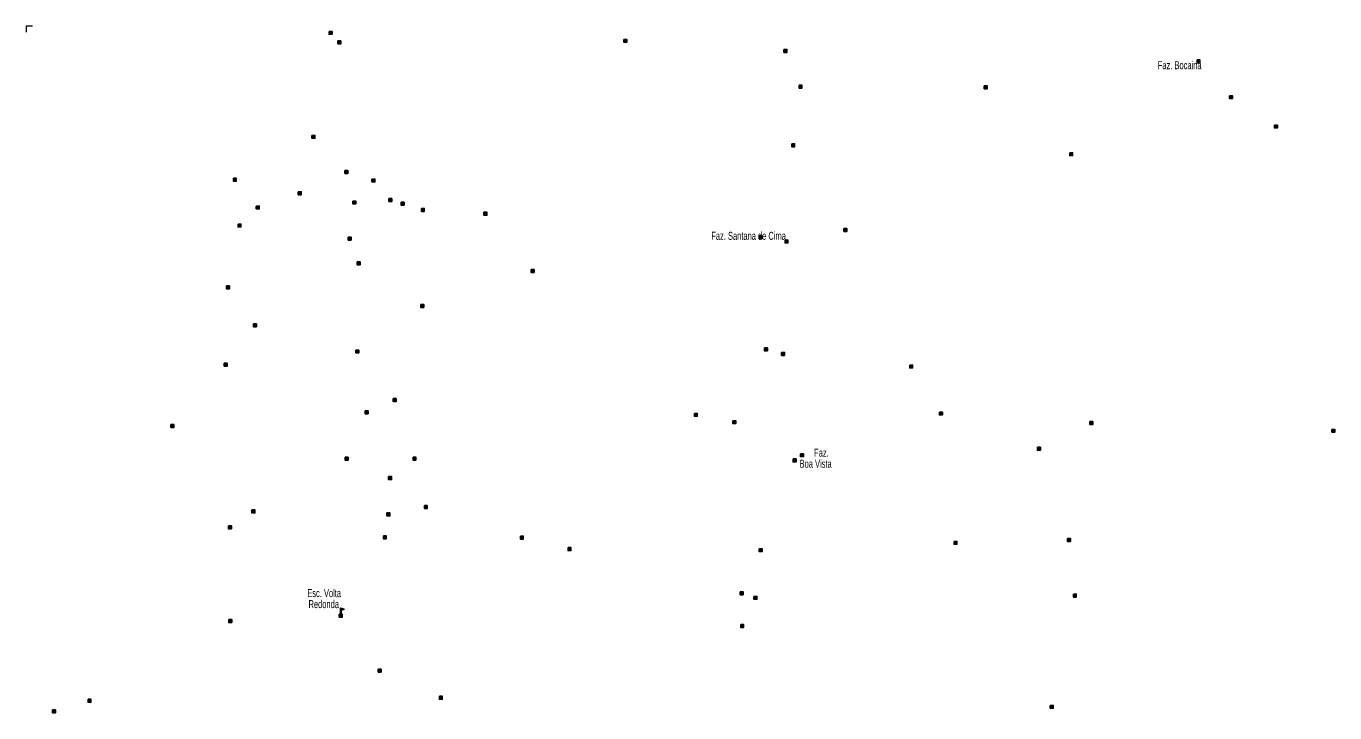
# Model space of a CAD drawing. Extents: x 447.8 to 473.9, y 7733.1 to 7760.8.
# Drawn here: x 447.77 to 460.86, y 7753.89 to 7760.75 of the extents above; entities that cross this region are included whole.
import ezdxf
from ezdxf.enums import TextEntityAlignment as Align

# ---------------------------------------------------------------- set-up
doc = ezdxf.new("R2010")
doc.units = 0
doc.header["$LTSCALE"] = 0.032
for name, color, linetype, lineweight in [('2', 7, 'Continuous', 25), ('4', 7, 'Continuous', 25), ('63', 7, 'Continuous', 13)]:
    doc.layers.add(name, color=color, linetype=linetype, lineweight=lineweight)
doc.layers.add('61', color=7, linetype='Continuous')

msp = doc.modelspace()

# ---------------------------------------------------------------- hatches: boundary and pattern name
at = {"layer": '2'}
for points in [[(450.8034, 7760.7022), (450.8324, 7760.7022), (450.8324, 7760.6732), (450.8034, 7760.6732)], [(450.8906, 7760.6068), (450.9196, 7760.6068), (450.9196, 7760.5778), (450.8906, 7760.5778)], [(453.7494, 7760.6225), (453.7784, 7760.6225), (453.7784, 7760.5935), (453.7494, 7760.5935)], [(455.3493, 7760.5218), (455.3783, 7760.5218), (455.3783, 7760.4928), (455.3493, 7760.4928)], [(459.4784, 7760.4165), (459.5074, 7760.4165), (459.5074, 7760.3875), (459.4784, 7760.3875)], [(455.5004, 7760.1648), (455.5294, 7760.1648), (455.5294, 7760.1358), (455.5004, 7760.1358)], [(457.352, 7760.1579), (457.381, 7760.1579), (457.381, 7760.1289), (457.352, 7760.1289)], [(459.8034, 7760.0595), (459.8324, 7760.0595), (459.8324, 7760.0305), (459.8034, 7760.0305)], [(460.252, 7759.7665), (460.281, 7759.7665), (460.281, 7759.7375), (460.252, 7759.7375)], [(450.6316, 7759.6634), (450.6606, 7759.6634), (450.6606, 7759.6344), (450.6316, 7759.6344)], [(455.4271, 7759.5788), (455.4561, 7759.5788), (455.4561, 7759.5498), (455.4271, 7759.5498)], [(458.2058, 7759.4895), (458.2348, 7759.4895), (458.2348, 7759.4605), (458.2058, 7759.4605)], [(449.8464, 7759.2354), (449.8754, 7759.2354), (449.8754, 7759.2064), (449.8464, 7759.2064)], [(450.9615, 7759.3117), (450.9905, 7759.3117), (450.9905, 7759.2827), (450.9615, 7759.2827)], [(451.2314, 7759.2272), (451.2604, 7759.2272), (451.2604, 7759.1982), (451.2314, 7759.1982)], [(450.4953, 7759.0991), (450.5243, 7759.0991), (450.5243, 7759.0701), (450.4953, 7759.0701)], [(451.0406, 7759.0064), (451.0696, 7759.0064), (451.0696, 7758.9774), (451.0406, 7758.9774)], [(451.4004, 7759.0309), (451.4294, 7759.0309), (451.4294, 7759.0019), (451.4004, 7759.0019)], [(451.5231, 7758.9955), (451.5521, 7758.9955), (451.5521, 7758.9665), (451.5231, 7758.9665)], [(450.0754, 7758.9573), (450.1044, 7758.9573), (450.1044, 7758.9283), (450.0754, 7758.9283)], [(451.7249, 7758.9328), (451.7539, 7758.9328), (451.7539, 7758.9038), (451.7249, 7758.9038)], [(452.3509, 7758.8944), (452.3799, 7758.8944), (452.3799, 7758.8654), (452.3509, 7758.8654)], [(449.8927, 7758.7774), (449.9217, 7758.7774), (449.9217, 7758.7484), (449.8927, 7758.7484)], [(455.949, 7758.7319), (455.978, 7758.7319), (455.978, 7758.7029), (455.949, 7758.7029)], [(450.9942, 7758.6465), (451.0232, 7758.6465), (451.0232, 7758.6175), (450.9942, 7758.6175)], [(455.1021, 7758.6587), (455.1311, 7758.6587), (455.1311, 7758.6297), (455.1021, 7758.6297)], [(455.3607, 7758.6175), (455.3897, 7758.6175), (455.3897, 7758.5885), (455.3607, 7758.5885)], [(451.0842, 7758.3984), (451.1132, 7758.3984), (451.1132, 7758.3694), (451.0842, 7758.3694)], [(452.8224, 7758.3222), (452.8514, 7758.3222), (452.8514, 7758.2932), (452.8224, 7758.2932)], [(449.7782, 7758.1585), (449.8072, 7758.1585), (449.8072, 7758.1295), (449.7782, 7758.1295)], [(451.7194, 7757.9731), (451.7484, 7757.9731), (451.7484, 7757.9441), (451.7194, 7757.9441)], [(450.0481, 7757.7795), (450.0771, 7757.7795), (450.0771, 7757.7505), (450.0481, 7757.7505)], [(455.1547, 7757.5394), (455.1837, 7757.5394), (455.1837, 7757.5104), (455.1547, 7757.5104)], [(451.0706, 7757.5178), (451.0996, 7757.5178), (451.0996, 7757.4888), (451.0706, 7757.4888)], [(455.3264, 7757.4937), (455.3554, 7757.4937), (455.3554, 7757.4647), (455.3264, 7757.4647)], [(449.7537, 7757.3869), (449.7827, 7757.3869), (449.7827, 7757.3579), (449.7537, 7757.3579)], [(456.6059, 7757.3678), (456.6349, 7757.3678), (456.6349, 7757.3388), (456.6059, 7757.3388)], [(451.4441, 7757.0325), (451.4731, 7757.0325), (451.4731, 7757.0035), (451.4441, 7757.0035)], [(451.1633, 7756.9098), (451.1923, 7756.9098), (451.1923, 7756.8808), (451.1633, 7756.8808)], [(454.4543, 7756.8848), (454.4833, 7756.8848), (454.4833, 7756.8558), (454.4543, 7756.8558)], [(456.9034, 7756.8986), (456.9324, 7756.8986), (456.9324, 7756.8696), (456.9034, 7756.8696)], [(449.222, 7756.7734), (449.251, 7756.7734), (449.251, 7756.7444), (449.222, 7756.7444)], [(454.8389, 7756.8116), (454.8679, 7756.8116), (454.8679, 7756.7826), (454.8389, 7756.7826)], [(458.4072, 7756.8024), (458.4362, 7756.8024), (458.4362, 7756.7734), (458.4072, 7756.7734)], [(460.8265, 7756.7246), (460.8555, 7756.7246), (460.8555, 7756.6956), (460.8265, 7756.6956)], [(455.5141, 7756.482), (455.5431, 7756.482), (455.5431, 7756.453), (455.5141, 7756.453)], [(457.8831, 7756.5461), (457.9121, 7756.5461), (457.9121, 7756.5171), (457.8831, 7756.5171)], [(450.9642, 7756.4463), (450.9932, 7756.4463), (450.9932, 7756.4173), (450.9642, 7756.4173)], [(451.6417, 7756.4471), (451.6707, 7756.4471), (451.6707, 7756.4181), (451.6417, 7756.4181)], [(455.4408, 7756.4293), (455.4698, 7756.4293), (455.4698, 7756.4003), (455.4408, 7756.4003)], [(451.3977, 7756.2527), (451.4267, 7756.2527), (451.4267, 7756.2237), (451.3977, 7756.2237)], [(451.7549, 7755.9637), (451.7839, 7755.9637), (451.7839, 7755.9347), (451.7549, 7755.9347)], [(450.0318, 7755.9201), (450.0608, 7755.9201), (450.0608, 7755.8911), (450.0318, 7755.8911)], [(451.3814, 7755.8901), (451.4104, 7755.8901), (451.4104, 7755.8611), (451.3814, 7755.8611)], [(449.7973, 7755.7619), (449.8263, 7755.7619), (449.8263, 7755.7329), (449.7973, 7755.7329)], [(451.3459, 7755.6611), (451.3749, 7755.6611), (451.3749, 7755.6321), (451.3459, 7755.6321)], [(452.7148, 7755.658), (452.7438, 7755.658), (452.7438, 7755.629), (452.7148, 7755.629)], [(457.0499, 7755.6054), (457.0789, 7755.6054), (457.0789, 7755.5764), (457.0499, 7755.5764)], [(458.1829, 7755.6351), (458.2119, 7755.6351), (458.2119, 7755.6061), (458.1829, 7755.6061)], [(453.1909, 7755.5436), (453.2199, 7755.5436), (453.2199, 7755.5146), (453.1909, 7755.5146)], [(455.1021, 7755.5321), (455.1311, 7755.5321), (455.1311, 7755.5031), (455.1021, 7755.5031)], [(454.9121, 7755.1018), (454.9411, 7755.1018), (454.9411, 7755.0728), (454.9121, 7755.0728)], [(455.0494, 7755.056), (455.0784, 7755.056), (455.0784, 7755.027), (455.0494, 7755.027)], [(458.2424, 7755.0789), (458.2714, 7755.0789), (458.2714, 7755.0499), (458.2424, 7755.0499)], [(449.8, 7754.8241), (449.829, 7754.8241), (449.829, 7754.7951), (449.8, 7754.7951)], [(454.9167, 7754.7745), (454.9457, 7754.7745), (454.9457, 7754.7455), (454.9167, 7754.7455)], [(451.2941, 7754.3279), (451.3231, 7754.3279), (451.3231, 7754.2989), (451.2941, 7754.2989)], [(448.3932, 7754.028), (448.4222, 7754.028), (448.4222, 7753.999), (448.3932, 7753.999)], [(451.9048, 7754.0579), (451.9338, 7754.0579), (451.9338, 7754.0289), (451.9048, 7754.0289)], [(448.0388, 7753.9216), (448.0678, 7753.9216), (448.0678, 7753.8926), (448.0388, 7753.8926)], [(458.0112, 7753.9665), (458.0402, 7753.9665), (458.0402, 7753.9375), (458.0112, 7753.9375)]]:
    msp.add_hatch(color=256, dxfattribs=at).paths.add_polyline_path(points)
at = {"layer": '4'}
msp.add_hatch(color=256, dxfattribs=at).paths.add_polyline_path([(450.9051, 7754.8475), (450.9051, 7754.8775), (450.9351, 7754.8775), (450.9351, 7754.8475)])

# ---------------------------------------------------------------- linework, layer by layer
at = {"layer": '2'}
for points in [[(450.8034, 7760.7022), (450.8324, 7760.7022), (450.8324, 7760.6732), (450.8034, 7760.6732)], [(450.8906, 7760.6068), (450.9196, 7760.6068), (450.9196, 7760.5778), (450.8906, 7760.5778)], [(453.7494, 7760.6225), (453.7784, 7760.6225), (453.7784, 7760.5935), (453.7494, 7760.5935)], [(455.3493, 7760.5218), (455.3783, 7760.5218), (455.3783, 7760.4928), (455.3493, 7760.4928)], [(459.4784, 7760.4165), (459.5074, 7760.4165), (459.5074, 7760.3875), (459.4784, 7760.3875)], [(455.5004, 7760.1648), (455.5294, 7760.1648), (455.5294, 7760.1358), (455.5004, 7760.1358)], [(457.352, 7760.1579), (457.381, 7760.1579), (457.381, 7760.1289), (457.352, 7760.1289)], [(459.8034, 7760.0595), (459.8324, 7760.0595), (459.8324, 7760.0305), (459.8034, 7760.0305)], [(460.252, 7759.7665), (460.281, 7759.7665), (460.281, 7759.7375), (460.252, 7759.7375)], [(450.6316, 7759.6634), (450.6606, 7759.6634), (450.6606, 7759.6344), (450.6316, 7759.6344)], [(455.4271, 7759.5788), (455.4561, 7759.5788), (455.4561, 7759.5498), (455.4271, 7759.5498)], [(458.2058, 7759.4895), (458.2348, 7759.4895), (458.2348, 7759.4605), (458.2058, 7759.4605)], [(449.8464, 7759.2354), (449.8754, 7759.2354), (449.8754, 7759.2064), (449.8464, 7759.2064)], [(450.9615, 7759.3117), (450.9905, 7759.3117), (450.9905, 7759.2827), (450.9615, 7759.2827)], [(451.2314, 7759.2272), (451.2604, 7759.2272), (451.2604, 7759.1982), (451.2314, 7759.1982)], [(450.4953, 7759.0991), (450.5243, 7759.0991), (450.5243, 7759.0701), (450.4953, 7759.0701)], [(451.0406, 7759.0064), (451.0696, 7759.0064), (451.0696, 7758.9774), (451.0406, 7758.9774)], [(451.4004, 7759.0309), (451.4294, 7759.0309), (451.4294, 7759.0019), (451.4004, 7759.0019)], [(451.5231, 7758.9955), (451.5521, 7758.9955), (451.5521, 7758.9665), (451.5231, 7758.9665)], [(450.0754, 7758.9573), (450.1044, 7758.9573), (450.1044, 7758.9283), (450.0754, 7758.9283)], [(451.7249, 7758.9328), (451.7539, 7758.9328), (451.7539, 7758.9038), (451.7249, 7758.9038)], [(452.3509, 7758.8944), (452.3799, 7758.8944), (452.3799, 7758.8654), (452.3509, 7758.8654)], [(449.8927, 7758.7774), (449.9217, 7758.7774), (449.9217, 7758.7484), (449.8927, 7758.7484)], [(455.949, 7758.7319), (455.978, 7758.7319), (455.978, 7758.7029), (455.949, 7758.7029)], [(450.9942, 7758.6465), (451.0232, 7758.6465), (451.0232, 7758.6175), (450.9942, 7758.6175)], [(455.1021, 7758.6587), (455.1311, 7758.6587), (455.1311, 7758.6297), (455.1021, 7758.6297)], [(455.3607, 7758.6175), (455.3897, 7758.6175), (455.3897, 7758.5885), (455.3607, 7758.5885)], [(451.0842, 7758.3984), (451.1132, 7758.3984), (451.1132, 7758.3694), (451.0842, 7758.3694)], [(452.8224, 7758.3222), (452.8514, 7758.3222), (452.8514, 7758.2932), (452.8224, 7758.2932)], [(449.7782, 7758.1585), (449.8072, 7758.1585), (449.8072, 7758.1295), (449.7782, 7758.1295)], [(451.7194, 7757.9731), (451.7484, 7757.9731), (451.7484, 7757.9441), (451.7194, 7757.9441)], [(450.0481, 7757.7795), (450.0771, 7757.7795), (450.0771, 7757.7505), (450.0481, 7757.7505)], [(455.1547, 7757.5394), (455.1837, 7757.5394), (455.1837, 7757.5104), (455.1547, 7757.5104)], [(451.0706, 7757.5178), (451.0996, 7757.5178), (451.0996, 7757.4888), (451.0706, 7757.4888)], [(455.3264, 7757.4937), (455.3554, 7757.4937), (455.3554, 7757.4647), (455.3264, 7757.4647)], [(449.7537, 7757.3869), (449.7827, 7757.3869), (449.7827, 7757.3579), (449.7537, 7757.3579)], [(456.6059, 7757.3678), (456.6349, 7757.3678), (456.6349, 7757.3388), (456.6059, 7757.3388)], [(451.4441, 7757.0325), (451.4731, 7757.0325), (451.4731, 7757.0035), (451.4441, 7757.0035)], [(451.1633, 7756.9098), (451.1923, 7756.9098), (451.1923, 7756.8808), (451.1633, 7756.8808)], [(454.4543, 7756.8848), (454.4833, 7756.8848), (454.4833, 7756.8558), (454.4543, 7756.8558)], [(456.9034, 7756.8986), (456.9324, 7756.8986), (456.9324, 7756.8696), (456.9034, 7756.8696)], [(449.222, 7756.7734), (449.251, 7756.7734), (449.251, 7756.7444), (449.222, 7756.7444)], [(454.8389, 7756.8116), (454.8679, 7756.8116), (454.8679, 7756.7826), (454.8389, 7756.7826)], [(458.4072, 7756.8024), (458.4362, 7756.8024), (458.4362, 7756.7734), (458.4072, 7756.7734)], [(460.8265, 7756.7246), (460.8555, 7756.7246), (460.8555, 7756.6956), (460.8265, 7756.6956)], [(455.5141, 7756.482), (455.5431, 7756.482), (455.5431, 7756.453), (455.5141, 7756.453)], [(457.8831, 7756.5461), (457.9121, 7756.5461), (457.9121, 7756.5171), (457.8831, 7756.5171)], [(450.9642, 7756.4463), (450.9932, 7756.4463), (450.9932, 7756.4173), (450.9642, 7756.4173)], [(451.6417, 7756.4471), (451.6707, 7756.4471), (451.6707, 7756.4181), (451.6417, 7756.4181)], [(455.4408, 7756.4293), (455.4698, 7756.4293), (455.4698, 7756.4003), (455.4408, 7756.4003)], [(451.3977, 7756.2527), (451.4267, 7756.2527), (451.4267, 7756.2237), (451.3977, 7756.2237)], [(451.7549, 7755.9637), (451.7839, 7755.9637), (451.7839, 7755.9347), (451.7549, 7755.9347)], [(450.0318, 7755.9201), (450.0608, 7755.9201), (450.0608, 7755.8911), (450.0318, 7755.8911)], [(451.3814, 7755.8901), (451.4104, 7755.8901), (451.4104, 7755.8611), (451.3814, 7755.8611)], [(449.7973, 7755.7619), (449.8263, 7755.7619), (449.8263, 7755.7329), (449.7973, 7755.7329)], [(451.3459, 7755.6611), (451.3749, 7755.6611), (451.3749, 7755.6321), (451.3459, 7755.6321)], [(452.7148, 7755.658), (452.7438, 7755.658), (452.7438, 7755.629), (452.7148, 7755.629)], [(457.0499, 7755.6054), (457.0789, 7755.6054), (457.0789, 7755.5764), (457.0499, 7755.5764)], [(458.1829, 7755.6351), (458.2119, 7755.6351), (458.2119, 7755.6061), (458.1829, 7755.6061)], [(453.1909, 7755.5436), (453.2199, 7755.5436), (453.2199, 7755.5146), (453.1909, 7755.5146)], [(455.1021, 7755.5321), (455.1311, 7755.5321), (455.1311, 7755.5031), (455.1021, 7755.5031)], [(454.9121, 7755.1018), (454.9411, 7755.1018), (454.9411, 7755.0728), (454.9121, 7755.0728)], [(455.0494, 7755.056), (455.0784, 7755.056), (455.0784, 7755.027), (455.0494, 7755.027)], [(458.2424, 7755.0789), (458.2714, 7755.0789), (458.2714, 7755.0499), (458.2424, 7755.0499)], [(449.8, 7754.8241), (449.829, 7754.8241), (449.829, 7754.7951), (449.8, 7754.7951)], [(454.9167, 7754.7745), (454.9457, 7754.7745), (454.9457, 7754.7455), (454.9167, 7754.7455)], [(451.2941, 7754.3279), (451.3231, 7754.3279), (451.3231, 7754.2989), (451.2941, 7754.2989)], [(448.3932, 7754.028), (448.4222, 7754.028), (448.4222, 7753.999), (448.3932, 7753.999)], [(451.9048, 7754.0579), (451.9338, 7754.0579), (451.9338, 7754.0289), (451.9048, 7754.0289)], [(448.0388, 7753.9216), (448.0678, 7753.9216), (448.0678, 7753.8926), (448.0388, 7753.8926)], [(458.0112, 7753.9665), (458.0402, 7753.9665), (458.0402, 7753.9375), (458.0112, 7753.9375)]]:
    msp.add_lwpolyline(points, close=True, dxfattribs=at)
at = {"layer": '4'}
msp.add_line((450.9176, 7754.8775), (450.9226, 7754.8775), dxfattribs=at)
for points in [[(450.9176, 7754.8775), (450.9176, 7754.94), (450.9526, 7754.9275), (450.9226, 7754.917), (450.9226, 7754.8775)], [(450.9051, 7754.8475), (450.9051, 7754.8775), (450.9351, 7754.8775), (450.9351, 7754.8475)]]:
    msp.add_lwpolyline(points, close=True, dxfattribs=at)
at = {"layer": '63'}
msp.add_lwpolyline([(447.8366, 7760.7544), (447.775, 7760.7544), (447.775, 7760.6937)], dxfattribs=at)

# ---------------------------------------------------------------- texts
at = {"layer": '61', "width": 0.7}
for s, p in [('Faz. Bocaina', (459.5232, 7760.3242)), ('Faz. Santana de Cima', (455.3683, 7758.6195)), ('Esc. Volta', (450.9222, 7755.0488)), ('Redonda ', (450.9222, 7754.9388))]:
    msp.add_text(s, height=0.08, dxfattribs=at).set_placement(p, align=Align.RIGHT)
for s, p in [('       Faz.', (455.5058, 7756.4518)), ('Boa Vista', (455.5058, 7756.3418))]:
    msp.add_text(s, height=0.08, dxfattribs=at).set_placement(p)

doc.saveas('drawing.dxf')
